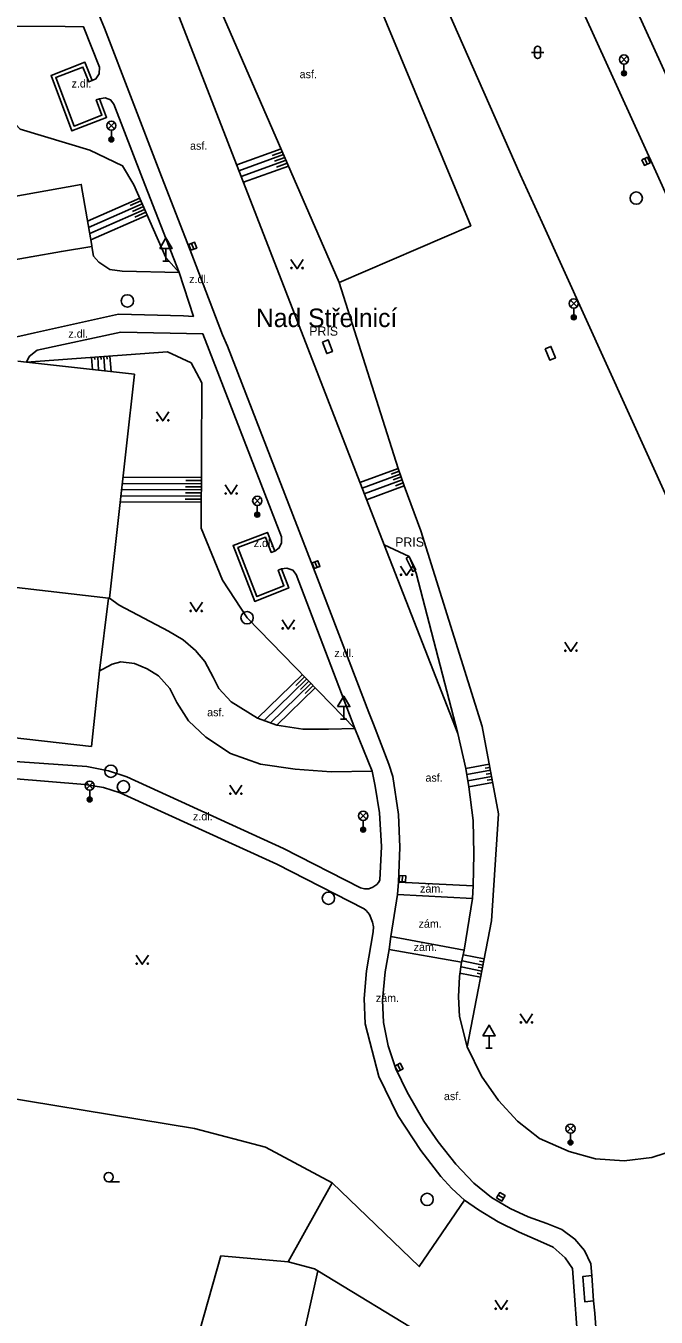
# Model space of a CAD drawing. Extents: x -598233 to -596890, y -1157848 to -1156431.
# Drawn here: x -597180.6 to -597129.4, y -1157373.5 to -1157268.7 of the extents above; entities that cross this region are included whole.
import ezdxf

# ---------------------------------------------------------------- set-up
doc = ezdxf.new("R2010")
doc.units = 0
for name, color, linetype in [('Level 10', 7, 'Continuous'), ('Level 11', 7, 'Continuous'), ('Level 14', 7, 'Continuous'), ('Level 15', 7, 'Continuous'), ('Level 24', 7, 'Continuous'), ('Level 27', 7, 'Continuous'), ('Level 33', 7, 'Continuous'), ('Level 34', 7, 'Continuous'), ('Level 36', 7, 'Continuous'), ('Level 40', 7, 'Continuous'), ('Level 41', 7, 'Continuous'), ('Level 49', 7, 'Continuous'), ('Level 5', 7, 'Continuous'), ('Level 7', 7, 'Continuous'), ('Level 8', 7, 'Continuous')]:
    doc.layers.add(name, color=color, linetype=linetype)

msp = doc.modelspace()

# ---------------------------------------------------------------- linework, layer by layer
at = {"layer": 'Level 10'}
for points in [[(-597149.69, -1157259.76), (-597140.43, -1157280.76)], [(-597151.48, -1157310.84), (-597158.39, -1157293.05), (-597164.17, -1157278.14), (-597171.13, -1157260.23)], [(-597150.78, -1157329.63), (-597151.09, -1157328.63), (-597152.34, -1157325.39), (-597152.71, -1157324.44), (-597156.89, -1157313.56), (-597164.2, -1157294.7), (-597164.59, -1157293.77), (-597166.75, -1157288.18), (-597167.1, -1157287.25), (-597169.68, -1157280.58), (-597174.19, -1157268.87), (-597174.45, -1157268.22), (-597174.56, -1157267.95), (-597176.4, -1157263.28), (-597176.78, -1157262.37)], [(-597136.23, -1157265.52), (-597129.42, -1157280.52), (-597122.2, -1157296.45), (-597108.92, -1157325.79)], [(-597140.43, -1157280.76), (-597138.65, -1157284.67), (-597121.46, -1157322.53), (-597113.09, -1157341.28)], [(-597145.49, -1157326.15), (-597151.48, -1157310.84)], [(-597145.49, -1157326.15), (-597144.85, -1157329), (-597144.6, -1157330.48), (-597144.26, -1157333.2199), (-597144.19, -1157335.96), (-597144.24, -1157338.53)], [(-597150.3, -1157338.2199), (-597150.19, -1157335.39), (-597150.31, -1157332.73), (-597150.78, -1157329.63)], [(-597150.4, -1157339.2199), (-597150.3, -1157338.2199)], [(-597150.92, -1157342.63), (-597150.4, -1157339.2199)], [(-597144.24, -1157338.53), (-597144.31, -1157339.55)], [(-597144.9699, -1157343.74), (-597144.31, -1157339.55)], [(-597151.08, -1157343.69), (-597150.92, -1157342.63)], [(-597151.4, -1157345.51), (-597151.08, -1157343.69)], [(-597145.37, -1157345.89), (-597145.2, -1157344.73)], [(-597145.2, -1157344.73), (-597144.9699, -1157343.74)], [(-597134.69, -1157369.21), (-597135.2, -1157368.14), (-597135.99, -1157367.2), (-597137.04, -1157366.42), (-597138.27, -1157365.93), (-597139.79, -1157365.39), (-597141.25, -1157364.7199), (-597142.77, -1157363.83), (-597144.19, -1157362.65), (-597145.6599, -1157361.12), (-597147.1, -1157359.3), (-597148.25, -1157357.63), (-597149.61, -1157355.28), (-597150.54, -1157353.37), (-597151.14, -1157351.51), (-597151.53, -1157349.62), (-597151.61, -1157347.8), (-597151.4, -1157345.51)], [(-597145.37, -1157345.89), (-597145.45, -1157347.54), (-597145.35, -1157349.12), (-597144.74, -1157351.58)], [(-597144.74, -1157351.58), (-597143.56, -1157353.98), (-597142.2, -1157355.96), (-597140.65, -1157357.63), (-597138.86, -1157359.03), (-597136.45, -1157360.08), (-597134.32, -1157360.7), (-597131.99, -1157360.85), (-597129.75, -1157360.58), (-597126.32, -1157359.4699)], [(-597134.6, -1157370.1599), (-597134.69, -1157369.21)], [(-597134.4699, -1157372.23), (-597134.6, -1157370.1599)], [(-597134.11, -1157376.7), (-597134.37, -1157373.2199), (-597134.4699, -1157372.23)]]:
    msp.add_lwpolyline(points, dxfattribs=at)
at = {"layer": 'Level 11'}
for points in [[(-597164.39, -1157253.98), (-597166.9, -1157262.46), (-597155.12, -1157289.53)], [(-597133.95, -1157260.84), (-597125.94, -1157278.43)], [(-597155.12, -1157289.53), (-597144.44, -1157284.92), (-597153.52, -1157263.03)], [(-597174.6, -1157272.05), (-597175.9, -1157268.77), (-597177.39, -1157268.75), (-597188.37, -1157268.73)], [(-597174.6, -1157272.05), (-597174.61, -1157272.6), (-597174.88, -1157272.99), (-597175.19, -1157273.14)], [(-597174.58, -1157274.61), (-597174.13, -1157274.53), (-597173.69, -1157274.7), (-597173.43, -1157275.06)], [(-597168.12, -1157288.71), (-597171.1, -1157281.09), (-597173.43, -1157275.06)], [(-597175.2199, -1157286.54), (-597176.08, -1157281.57), (-597189.86, -1157284.03), (-597189.1, -1157288.3)], [(-597175.21, -1157286.62), (-597177.68, -1157287.01), (-597180.15, -1157287.44), (-597182.61, -1157287.89), (-597185.9, -1157288.46), (-597189.61, -1157289.02)], [(-597175.21, -1157286.62), (-597175.2199, -1157286.54)], [(-597175.07, -1157287.38), (-597175.21, -1157286.62)], [(-597172.75, -1157288.62), (-597173.76, -1157288.4699), (-597174.65, -1157287.89), (-597175.07, -1157287.38)], [(-597168.12, -1157288.71), (-597166.96, -1157292.29), (-597167.78, -1157292.25), (-597173.04, -1157292.11), (-597179.88, -1157293.61)], [(-597168.12, -1157288.71), (-597172.75, -1157288.62)], [(-597179.88, -1157293.61), (-597181.9, -1157294.07), (-597183.63, -1157294.14)], [(-597159.82, -1157310.19), (-597166.21, -1157293.69), (-597172.87, -1157293.57), (-597179.65, -1157295.03)], [(-597179.65, -1157295.03), (-597180.29, -1157295.55), (-597180.53, -1157296)], [(-597159.82, -1157310.19), (-597159.8, -1157310.68), (-597160, -1157311.08), (-597160.36, -1157311.34)], [(-597159.8, -1157312.79), (-597159.37, -1157312.7199), (-597158.89, -1157312.89), (-597158.63, -1157313.23)], [(-597153.87, -1157325.74), (-597158.63, -1157313.23)], [(-597173, -1157315.7199), (-597173.78, -1157315.1599)], [(-597173, -1157315.7199), (-597168.99, -1157317.83), (-597167.79, -1157318.54), (-597166.8, -1157319.4), (-597166.05, -1157320.31), (-597165.36, -1157321.58), (-597164.9, -1157322.5), (-597163.9, -1157323.59), (-597161.75, -1157324.9), (-597160.19, -1157325.4699), (-597158.08, -1157325.81), (-597156, -1157325.81)], [(-597152.45, -1157329.2), (-597155.79, -1157329.27), (-597158.7, -1157329.05), (-597161.52, -1157328.64), (-597163.95, -1157327.77), (-597165.96, -1157326.45), (-597167.37, -1157325.13), (-597168.32, -1157323.64), (-597168.89, -1157322.5), (-597169.8, -1157321.48), (-597170.71, -1157320.89), (-597171.76, -1157320.4699), (-597172.87, -1157320.32), (-597173.56, -1157320.52), (-597174.31, -1157320.94)], [(-597174.6, -1157321.06), (-597174.31, -1157320.94)], [(-597156, -1157325.81), (-597153.87, -1157325.74)], [(-597152.45, -1157329.2), (-597153.87, -1157325.74)], [(-597175.62, -1157328.82), (-597184.58, -1157328.2)], [(-597172.38, -1157329.68), (-597173.86, -1157329.17), (-597175.62, -1157328.82)], [(-597175.77, -1157330.29), (-597184.6599, -1157329.57)], [(-597172.38, -1157329.68), (-597159.64, -1157335.48), (-597153.4099, -1157338.67)], [(-597151.84, -1157338.07), (-597151.7, -1157335.32), (-597151.86, -1157332.58), (-597152.21, -1157330.42), (-597152.45, -1157329.2)], [(-597172.92, -1157330.98), (-597174.28, -1157330.53), (-597175.77, -1157330.29)], [(-597153.1, -1157340.38), (-597160.2, -1157336.75), (-597172.92, -1157330.98)], [(-597153.41, -1157338.67), (-597153.07, -1157338.76), (-597152.72, -1157338.75), (-597152.39, -1157338.64), (-597152.07, -1157338.4), (-597151.93, -1157338.24), (-597151.84, -1157338.07)], [(-597150.3, -1157338.2199), (-597144.24, -1157338.53)], [(-597150.4, -1157339.2199), (-597144.31, -1157339.55)], [(-597153.1, -1157340.38), (-597152.94, -1157340.53), (-597152.67, -1157340.86), (-597152.41, -1157341.46), (-597152.35, -1157341.86), (-597152.37, -1157342.26)], [(-597152.9, -1157345.4099), (-597152.37, -1157342.26)], [(-597150.92, -1157342.63), (-597144.9699, -1157343.74)], [(-597151.08, -1157343.69), (-597145.2, -1157344.73)], [(-597144.95, -1157364.05), (-597145.9699, -1157363.09), (-597146.86, -1157362.12), (-597148.5, -1157360.02), (-597150.37, -1157357.1599), (-597151.9099, -1157354), (-597153.02, -1157349.73), (-597153.11, -1157347.6599), (-597152.9, -1157345.4099)], [(-597136.18, -1157369.6), (-597136.78, -1157368.73), (-597137.76, -1157367.87), (-597138.79, -1157367.39), (-597140.52, -1157366.65), (-597142.21, -1157365.79), (-597143.81, -1157364.83), (-597144.95, -1157364.05)], [(-597135.6599, -1157376.57), (-597136.18, -1157369.6)], [(-597134.6, -1157370.1599), (-597135.34, -1157370.24), (-597135.19, -1157372.29), (-597134.4699, -1157372.23)]]:
    msp.add_lwpolyline(points, dxfattribs=at)
at = {"layer": 'Level 14'}
for points in [[(-597168.12, -1157288.71), (-597169.21, -1157287.5), (-597171.8, -1157281.61), (-597172.7199, -1157280.07), (-597175.39, -1157278.79), (-597181.04, -1157277.07), (-597182.86, -1157275.1599), (-597184.68, -1157272.68), (-597185.54, -1157270.04), (-597188.37, -1157268.73)], [(-597144.74, -1157351.58), (-597142.76, -1157341.37), (-597142.2, -1157332.68), (-597143.51, -1157325.58), (-597148.51, -1157309.7), (-597149.84, -1157306.03), (-597150.35, -1157304.62), (-597155.12, -1157289.53)], [(-597180.53, -1157296), (-597169.06, -1157295.15), (-597167.15, -1157296.05), (-597166.28, -1157297.68), (-597166.33, -1157309.4699), (-597164.6, -1157313.71), (-597162.61, -1157316.75), (-597153.87, -1157325.74)], [(-597151.48, -1157310.84), (-597149.45, -1157311.77), (-597148.88, -1157313.13)], [(-597148.88, -1157313.13), (-597145.49, -1157326.15)]]:
    msp.add_lwpolyline(points, dxfattribs=at)
at = {"layer": 'Level 15'}
for points in [[(-597159.84, -1157278.69), (-597163.45, -1157279.99)], [(-597159.64, -1157279.15), (-597163.27, -1157280.46)], [(-597159.44, -1157279.61), (-597163.09, -1157280.92)], [(-597159.74, -1157278.93), (-597160.56, -1157279.2199)], [(-597159.54, -1157279.39), (-597160.39, -1157279.69)], [(-597159.24, -1157280.08), (-597162.9099, -1157281.39)], [(-597159.34, -1157279.85), (-597160.2199, -1157280.1599)], [(-597171.33, -1157282.69), (-597175.56, -1157284.55)], [(-597171.13, -1157283.14), (-597175.48, -1157285.06)], [(-597170.93, -1157283.6), (-597175.39, -1157285.56)], [(-597171.23, -1157282.9099), (-597172.09, -1157283.29)], [(-597171.03, -1157283.37), (-597171.9099, -1157283.76)], [(-597170.82, -1157283.83), (-597171.73, -1157284.23)], [(-597170.7199, -1157284.06), (-597175.3, -1157286.07)], [(-597175.23, -1157295.61), (-597175.1599, -1157296.59)], [(-597174.99, -1157295.59), (-597174.9699, -1157295.79)], [(-597174.74, -1157295.57), (-597174.6599, -1157296.65)], [(-597174.49, -1157295.55), (-597174.4699, -1157295.77)], [(-597174.24, -1157295.53), (-597174.15, -1157296.7)], [(-597173.99, -1157295.51), (-597173.9699, -1157295.76)], [(-597173.74, -1157295.5), (-597173.65, -1157296.76)], [(-597150.35, -1157304.62), (-597153.45, -1157305.77)], [(-597150.26, -1157304.85), (-597150.9099, -1157305.09)], [(-597166.31, -1157305.87), (-597172.74, -1157305.84)], [(-597166.31, -1157305.37), (-597172.68, -1157305.34)], [(-597166.31, -1157305.62), (-597167.59, -1157305.62)], [(-597150.18, -1157305.09), (-597153.27, -1157306.23)], [(-597150.01, -1157305.56), (-597153.09, -1157306.7)], [(-597150.09, -1157305.32), (-597150.74, -1157305.56)], [(-597149.92, -1157305.79), (-597150.56, -1157306.03)], [(-597166.32, -1157306.87), (-597172.85, -1157306.84)], [(-597166.32, -1157306.37), (-597172.79, -1157306.34)], [(-597166.32, -1157306.62), (-597167.62, -1157306.62)], [(-597166.32, -1157306.12), (-597167.61, -1157306.12)], [(-597149.84, -1157306.03), (-597152.9099, -1157307.17)], [(-597166.32, -1157307.37), (-597172.9, -1157307.34)], [(-597166.32, -1157307.12), (-597167.63, -1157307.12)], [(-597158.12, -1157321.37), (-597161.75, -1157324.9)], [(-597157.95, -1157321.55), (-597158.6599, -1157322.24)], [(-597157.77, -1157321.73), (-597161.25, -1157325.11)], [(-597157.42, -1157322.08), (-597160.73, -1157325.3)], [(-597157.07, -1157322.44), (-597160.19, -1157325.4699)], [(-597157.6, -1157321.9099), (-597158.28, -1157322.57)], [(-597157.25, -1157322.26), (-597157.89, -1157322.89)], [(-597142.94, -1157328.65), (-597144.85, -1157329)], [(-597142.9, -1157328.9), (-597143.28, -1157328.9699)], [(-597142.85, -1157329.14), (-597144.76, -1157329.49)], [(-597142.76, -1157329.63), (-597144.68, -1157329.99)], [(-597142.81, -1157329.39), (-597143.19, -1157329.46)], [(-597142.7199, -1157329.88), (-597143.1, -1157329.95)], [(-597142.67, -1157330.13), (-597144.6, -1157330.48)], [(-597143.45, -1157344.95), (-597145.13, -1157344.62)], [(-597143.36, -1157344.46), (-597145.04, -1157344.13)], [(-597143.4099, -1157344.7), (-597143.74, -1157344.64)], [(-597143.64, -1157345.93), (-597145.32, -1157345.6)], [(-597143.55, -1157345.44), (-597145.23, -1157345.11)], [(-597143.6, -1157345.68), (-597143.93, -1157345.62)], [(-597143.5, -1157345.19), (-597143.84, -1157345.13)]]:
    msp.add_lwpolyline(points, dxfattribs=at)
at = {"layer": 'Level 24'}
for points in [[(-597156.4892, -1157294.3691), (-597156.1392, -1157295.3059), (-597155.6708, -1157295.1309), (-597156.0208, -1157294.1941)], [(-597138.3936, -1157294.904), (-597138.0327, -1157295.8365), (-597137.5664, -1157295.656), (-597137.9273, -1157294.7235)]]:
    msp.add_lwpolyline(points, close=True, dxfattribs=at)
msp.add_lwpolyline([(-597149.7, -1157311.92), (-597149.45, -1157311.77), (-597148.9099, -1157312.85), (-597149.1599, -1157312.99), (-597149.7, -1157311.92)], dxfattribs=at)
at = {"layer": 'Level 27'}
for p, q in [((-597130.3113, -1157279.4615), (-597130.1087, -1157279.9185)), ((-597167.108, -1157286.356), (-597166.932, -1157286.824)), ((-597157.098, -1157312.206), (-597156.922, -1157312.674)), ((-597149.9755, -1157337.6904), (-597150.0045, -1157338.1896)), ((-597150.3852, -1157353.0381), (-597150.1548, -1157353.4819)), ((-597142.2171, -1157363.646), (-597141.7829, -1157363.894))]:
    msp.add_line(p, q, dxfattribs=at)
for points in [[(-597130.5399, -1157279.5628), (-597130.3372, -1157280.0199), (-597129.8801, -1157279.8172), (-597130.0828, -1157279.3601)], [(-597167.342, -1157286.4441), (-597167.1659, -1157286.912), (-597166.698, -1157286.7359), (-597166.8741, -1157286.268)], [(-597157.332, -1157312.2941), (-597157.1559, -1157312.762), (-597156.688, -1157312.5859), (-597156.8641, -1157312.118)], [(-597150.2251, -1157337.6759), (-597150.2541, -1157338.1751), (-597149.7549, -1157338.2041), (-597149.7259, -1157337.7049)], [(-597150.6071, -1157353.1533), (-597150.3767, -1157353.5971), (-597149.9329, -1157353.3667), (-597150.1633, -1157352.9229)], [(-597142.3411, -1157363.8631), (-597141.9069, -1157364.1111), (-597141.6589, -1157363.6769), (-597142.0931, -1157363.4289)]]:
    msp.add_lwpolyline(points, close=True, dxfattribs=at)
for centre in [(-597131, -1157282.68), (-597172.33, -1157291.03), (-597162.61, -1157316.75), (-597173.67, -1157329.2199), (-597172.65, -1157330.48), (-597156, -1157339.53), (-597147.99, -1157363.98)]:
    msp.add_circle(centre, 0.5, dxfattribs=at)
at = {"layer": 'Level 33'}
for p, q in [((-597132.265, -1157271.69), (-597131.735, -1157271.16)), ((-597132.265, -1157271.16), (-597131.735, -1157271.69)), ((-597132, -1157271.8), (-597132, -1157272.55)), ((-597173.895, -1157277.06), (-597173.365, -1157276.53)), ((-597173.895, -1157276.53), (-597173.365, -1157277.06)), ((-597173.63, -1157277.17), (-597173.63, -1157277.92)), ((-597136.345, -1157291.5), (-597135.815, -1157290.97)), ((-597136.345, -1157290.97), (-597135.815, -1157291.5)), ((-597136.08, -1157291.61), (-597136.08, -1157292.36)), ((-597162.045, -1157307.52), (-597161.515, -1157306.99)), ((-597162.045, -1157306.99), (-597161.515, -1157307.52)), ((-597161.78, -1157307.63), (-597161.78, -1157308.38)), ((-597175.655, -1157330.65), (-597175.125, -1157330.12)), ((-597175.655, -1157330.12), (-597175.125, -1157330.65)), ((-597175.39, -1157330.76), (-597175.39, -1157331.51)), ((-597153.445, -1157333.1), (-597152.915, -1157332.57)), ((-597153.445, -1157332.57), (-597152.915, -1157333.1)), ((-597153.18, -1157333.21), (-597153.18, -1157333.96)), ((-597136.605, -1157358.5), (-597136.075, -1157357.97)), ((-597136.605, -1157357.97), (-597136.075, -1157358.5)), ((-597136.34, -1157358.61), (-597136.34, -1157359.36))]:
    msp.add_line(p, q, dxfattribs=at)
for centre, radius in [((-597132, -1157271.425), 0.375), ((-597132, -1157272.55), 0.2), ((-597132, -1157272.55), 0.1445), ((-597132, -1157272.55), 0.0876), ((-597173.63, -1157276.795), 0.375), ((-597173.63, -1157277.92), 0.2), ((-597173.63, -1157277.92), 0.1445), ((-597173.63, -1157277.92), 0.0876), ((-597136.08, -1157291.235), 0.375), ((-597136.08, -1157292.36), 0.2), ((-597136.08, -1157292.36), 0.1445), ((-597136.08, -1157292.36), 0.0876), ((-597161.78, -1157307.255), 0.375), ((-597161.78, -1157308.38), 0.2), ((-597161.78, -1157308.38), 0.1445), ((-597161.78, -1157308.38), 0.0876), ((-597175.39, -1157330.385), 0.375), ((-597175.39, -1157331.51), 0.2), ((-597175.39, -1157331.51), 0.1445), ((-597175.39, -1157331.51), 0.0876), ((-597153.18, -1157332.835), 0.375), ((-597153.18, -1157333.96), 0.2), ((-597153.18, -1157333.96), 0.1445), ((-597153.18, -1157333.96), 0.0876), ((-597136.34, -1157358.235), 0.375), ((-597136.34, -1157359.36), 0.2), ((-597136.34, -1157359.36), 0.1445), ((-597136.34, -1157359.36), 0.0876)]:
    msp.add_circle(centre, radius, dxfattribs=at)
at = {"layer": 'Level 34'}
for p, q in [((-597169.2, -1157286.782), (-597169.2, -1157287.8)), ((-597169.45, -1157287.8), (-597168.95, -1157287.8)), ((-597154.76, -1157323.972), (-597154.76, -1157324.99)), ((-597155.01, -1157324.99), (-597154.51, -1157324.99)), ((-597142.96, -1157350.692), (-597142.96, -1157351.71)), ((-597143.21, -1157351.71), (-597142.71, -1157351.71))]:
    msp.add_line(p, q, dxfattribs=at)
for points in [[(-597169.7, -1157286.782), (-597168.7, -1157286.782), (-597169.2, -1157285.916)], [(-597155.26, -1157323.972), (-597154.26, -1157323.972), (-597154.76, -1157323.106)], [(-597143.46, -1157350.692), (-597142.46, -1157350.692), (-597142.96, -1157349.826)]]:
    msp.add_lwpolyline(points, close=True, dxfattribs=at)
at = {"layer": 'Level 36'}
for p, q in [((-597139.516, -1157270.846), (-597138.516, -1157270.846)), ((-597139.266, -1157270.596), (-597139.266, -1157271.096)), ((-597138.766, -1157270.596), (-597138.766, -1157271.096)), ((-597173.85, -1157362.545), (-597172.975, -1157362.545))]:
    msp.add_line(p, q, dxfattribs=at)
for points in [[(-597159.05, -1157287.6599), (-597158.55, -1157288.4099), (-597158.05, -1157287.6599)], [(-597169.95, -1157300.02), (-597169.45, -1157300.77), (-597168.95, -1157300.02)], [(-597164.4, -1157305.96), (-597163.9, -1157306.71), (-597163.4, -1157305.96)], [(-597150.15, -1157312.56), (-597149.65, -1157313.31), (-597149.15, -1157312.56)], [(-597167.24, -1157315.5), (-597166.74, -1157316.25), (-597166.24, -1157315.5)], [(-597159.76, -1157316.92), (-597159.26, -1157317.67), (-597158.76, -1157316.92)], [(-597136.81, -1157318.73), (-597136.31, -1157319.48), (-597135.81, -1157318.73)], [(-597164.02, -1157330.34), (-597163.52, -1157331.09), (-597163.02, -1157330.34)], [(-597171.62, -1157344.14), (-597171.12, -1157344.89), (-597170.62, -1157344.14)], [(-597140.42, -1157348.9099), (-597139.92, -1157349.6599), (-597139.42, -1157348.9099)], [(-597142.4699, -1157372.1599), (-597141.9699, -1157372.9099), (-597141.4699, -1157372.1599)]]:
    msp.add_lwpolyline(points, dxfattribs=at)
for centre, radius in [((-597159.0002, -1157288.3597), 0.05), ((-597158.1008, -1157288.3597), 0.05), ((-597169.9002, -1157300.7198), 0.05), ((-597169.0008, -1157300.7198), 0.05), ((-597164.3502, -1157306.6598), 0.05), ((-597163.4508, -1157306.6598), 0.05), ((-597150.1002, -1157313.2598), 0.05), ((-597149.2008, -1157313.2598), 0.05), ((-597167.1902, -1157316.1998), 0.05), ((-597166.2908, -1157316.1998), 0.05), ((-597159.7102, -1157317.6198), 0.05), ((-597158.8108, -1157317.6198), 0.05), ((-597136.7602, -1157319.4298), 0.05), ((-597135.8608, -1157319.4298), 0.05), ((-597163.9702, -1157331.0398), 0.05), ((-597163.0708, -1157331.0398), 0.05), ((-597171.5702, -1157344.8398), 0.05), ((-597170.6708, -1157344.8398), 0.05), ((-597140.3702, -1157349.6097), 0.05), ((-597139.4708, -1157349.6097), 0.05), ((-597173.8501, -1157362.1699), 0.375), ((-597142.4201, -1157372.8597), 0.05), ((-597141.5207, -1157372.8597), 0.05)]:
    msp.add_circle(centre, radius, dxfattribs=at)
for centre, start, end in [((-597139.0157, -1157270.5963), 0, 180), ((-597139.0157, -1157271.0963), 180, 0)]:
    msp.add_arc(centre, 0.25, start, end, dxfattribs=at)
at = {"layer": 'Level 5'}
for points in [[(-597181.2199, -1157295.92), (-597180.53, -1157296)], [(-597180.53, -1157296), (-597171.74, -1157296.9699)], [(-597171.74, -1157296.9699), (-597173.78, -1157315.1599)], [(-597193.74, -1157312.87), (-597173.86, -1157315.15)], [(-597173.86, -1157315.15), (-597174.6, -1157321.06)], [(-597173.86, -1157315.15), (-597173.78, -1157315.1599)], [(-597174.6, -1157321.06), (-597175.25, -1157327.21)], [(-597195.09, -1157324.96), (-597175.25, -1157327.21)]]:
    msp.add_lwpolyline(points, dxfattribs=at)
at = {"layer": 'Level 7'}
for points in [[(-597175.19, -1157273.14), (-597175.77, -1157271.65), (-597178.53, -1157272.71), (-597176.83, -1157277.2199), (-597174.02, -1157276.12), (-597174.58, -1157274.61)], [(-597175.19, -1157273.14), (-597175.4699, -1157273.25), (-597175.94, -1157272.04), (-597178.14, -1157272.88), (-597176.6599, -1157276.83), (-597174.4, -1157275.95), (-597174.86, -1157274.71), (-597174.58, -1157274.61)], [(-597160.36, -1157311.34), (-597160.95, -1157309.83), (-597163.74, -1157310.88), (-597161.98, -1157315.42), (-597159.2199, -1157314.33), (-597159.8, -1157312.79)], [(-597160.36, -1157311.34), (-597160.64, -1157311.45), (-597161.12, -1157310.2199), (-597163.35, -1157311.05), (-597161.81, -1157315.03), (-597159.61, -1157314.1599), (-597160.08, -1157312.9), (-597159.8, -1157312.79)], [(-597155.69, -1157362.63), (-597161.1, -1157359.74), (-597166.87, -1157358.2199), (-597187.29, -1157354.87)], [(-597159.26, -1157369.04), (-597155.69, -1157362.63)], [(-597155.69, -1157362.63), (-597148.62, -1157369.43), (-597144.95, -1157364.05)], [(-597167.84, -1157379.57), (-597164.73, -1157368.57), (-597159.26, -1157369.04)], [(-597163.9099, -1157401.39), (-597156.86, -1157369.79)], [(-597157.14, -1157369.62), (-597156.86, -1157369.79)], [(-597156.86, -1157369.79), (-597147.96, -1157375.19), (-597146.83, -1157376.04)]]:
    msp.add_lwpolyline(points, dxfattribs=at)
at = {"layer": 'Level 8'}
msp.add_lwpolyline([(-597159.26, -1157369.04), (-597157.14, -1157369.62)], dxfattribs=at)

# ---------------------------------------------------------------- texts
at = {"layer": 'Level 40'}
for s, p in [('asf.', (-597158.34, -1157272.94)), ('z.dl.', (-597176.86, -1157273.7)), ('asf.', (-597167.24, -1157278.75)), ('z.dl.', (-597167.31, -1157289.58)), ('z.dl.', (-597177.12, -1157294.01)), ('z.dl.', (-597162.07, -1157311.01)), ('z.dl.', (-597155.52, -1157319.95)), ('asf.', (-597165.85, -1157324.75)), ('asf.', (-597148.12, -1157330.06)), ('z.dl.', (-597167, -1157333.2)), ('zám.', (-597148.56, -1157339.07)), ('zám.', (-597148.68, -1157341.92)), ('zám.', (-597149.08, -1157343.81)), ('zám.', (-597152.15, -1157347.95)), ('asf.', (-597146.62, -1157355.92))]:
    msp.add_text(s, height=0.65, dxfattribs=at).set_placement(p)
at = {"layer": 'Level 41'}
for p in [(-597157.56, -1157293.85), (-597150.58, -1157310.98)]:
    msp.add_text('PRIS', height=0.75, dxfattribs=at).set_placement(p)
at = {"layer": 'Level 49'}
msp.add_text('Nad Střelnicí', height=1.5, dxfattribs=at).set_placement((-597161.89, -1157293.15))

doc.saveas('drawing.dxf')
